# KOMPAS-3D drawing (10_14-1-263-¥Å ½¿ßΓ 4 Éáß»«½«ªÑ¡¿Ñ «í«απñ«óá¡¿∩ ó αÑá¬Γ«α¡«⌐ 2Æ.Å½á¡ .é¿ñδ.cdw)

Views: Вид 1, Вид 2, Вид 3
Referenced files in C:\Program Files\ASCON\KOMPAS-3D V10\Sys\: Graphic.lcs
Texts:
  Стена
  Металлич. перекрытия
  Сэндвич-панели 100
  Блоки фундаментные 400
  Сэндвич-панели 150
  Текст на чертеже
  Размерные надписи
  Шероховатость
  Линия-выноска #1
  Линия-выноска #2
  Линия-выноска #3
  Отклонения формы и база
  Заголовок таблицы
  Ячейка таблицы
  Стрелка вида
  Обозначение изменения
  Фигурная скобка
  Номер узла
  Марка координационной оси
  VRCB
  Выносная надпись
  Обозначение узла
  Марка/позиционное обозначение с линией-выноской
  Марка/позиционное обозначение на линии
  Марка/позиционное обозначение без линии-выноски
  Normal
  txt
  Body Text
  heading 1
  Знак Знак Знак Знак Знак Знак
  Verdana
  Лит-Масса-Масштаб
  Материал-Предприятие
  MS Sans Serif
  Simplex
  Txt
  Title Specification
  Body Specification ( left align )
  Body Specificaton ( centered )
  Без имени
  Additional DXF text style 0
  Обычный
  Термин
  Список определений
  Адрес
  Цитаты
  Форматированный
  Courier New
  Z-конец формы
  Z-начало формы
  ТекстШаг1
  Денис
  heading 2
  AGOpus
  footer
  Title
  ООббыыччнныыйй
  Definition Term
  Definition List
  Address
  Blockquote
  Preformatted
  z-Bottom of Form
  z-Top of Form
  TXT
  header
  heading 8
  heading 3
  heading 6
  heading 7
  russ
  ТТееррммиинн
  ССппииссоокк ооппррееддееллеенниийй
  ААддрреесс
  ЦЦииттааттыы
  ФФооррммааттиирроовваанннныыйй
  Z-ккооннеецц ффооррммыы
  Z-ннааччааллоо ффооррммыы
  Абзац Знак
  heading 4
  heading 5
  heading 9
  GOST 2.304 type A
  rustxt
  цепи
  ссылки
  Маркировка
  Подпись в квадратике
  табл
  ЗОНА_привяз
  маркировка
  ГОСТ_МНЕ
  ESK - Обозначение
  текст переноса
  Тексты. 3,2
  Body Text 3
  клеммы, контакты
  тексты табл
  ISOCP
  HeliosLight
  Pa3
  Pa1
  Шрифт 2.5
  Заголовки
  RUSTXT
  NormalParagraphStyle
  Три с половиной
  style2
  Table Contents
  Table Heading
  Tahoma
  FR5
  Текст 3,5
  Subtitle
  romanc
  eskd1
  Pa15
  Pa18
  CNBNDG+TimesNewRoman
  Аппараты
  подписи
  Состав чартежа
  ячейка табл.
  Ссылки
  Пояснения
  Клеммник текст
  CM12
  romans
  gif
  Пояснения 2
  текст табл
  ISOCPEUR
  CC С?т?и?л?ь? П?о? ц?е?н?т?р?у?
  Courier New Cyr
  ROMANS
  SIMPLEX
  Обычный (веб)
  .07 RGB_0_0_0 i0b0u0
  Body Text Indent 3
  Основной текст с отступом 3
  надписи
  экспликация
  Здание
  Оси
  Перечень оборудования
  Поз.
  Кол.
  ед., кг
  Приме-
  чание
  Реактор токоограничивающий 6 кВ
  РТСТ 6-3200-0,35 УХЛ3 (компл. 3 фазы)
  Опорный изолятор 10 кВ
  ИО-10-3,75-II-У3
  Проходной изолятор 10 кВ
  ИПУ-10/3150-12,5-УХЛ1
  Шина алюминиевая 2хAl-100 10
  Шкаф собственных нужд
  реакторной 2Т
  см. п.п.14
  см. п.п.4
  Примечания:
  1. Предусмотреть односкатную кровлю, со скатом в сторону оси А.
  2. Предусмотреть возможность демонтажа и повторной установки крыши и стены по оси 3 для
  ремонтных работ с реакторами.
  3. Предусмотреть несущую конструкцию  пола.
  4. В комплект поставки включить:
  - проходные изоляторы в количестве 6 шт.,
  - опорные изоляторы, жесткую ошиновку и арматуру для её крепления к изоляторам в количестве,
  достаточном для выполнения трассы разводки жесткой ошиновки по стенам и подключения
  реакторов,в соответствии с планом
  здания реакторной.
  - оборудование для организации силовой и осветительной сети в соответствии с 10/14-1-263-ЭП
  лист 6.
  - шкаф собственных нужд реакторной см. 10/14-1-263 лист 6.
  - крылечные металлическую лестницы.
  5. Выполнить разводку жесткой ошиновки по стенам, установку проходных изоляторов и крепление к
  ним ошиновки. Трасса разводки жесткой ошиновки должна удовлетворять требованиям ПУЭ 7 издание.
  Междуфазные расстояния принять не менее 500 мм ,длину пролета между опорными изоляторами
  принять не более 800 мм.
  6. Предусмотреть входные металлические двери- 2100х800 мм.
  7. Для предотвращения прикосновения к неизолированным токоведущим частям в здании реакторной
  предусмотреть съемное сетчатое ограждение высотой 1900 мм.
  8. На полу предусмотреть опалубку для заливки бетонной подушки.
  9. В полу под шкафом собственных нужд реакторной предусмотреть технологическое отверстия
  диаметром 60 мм.
  10. В местах подвеса  натяжных гирлянд предусмотреть усиление конструкции, с закладной деталью и
  узлом крепления типа КГП-7-1.
  11. Установку проходных изоляторов выполнить в соответствии с требованиями СНиП 3.05.06-85. Над
  проходными изоляторами по оси А предусмотреть защитный козырек.
  12. Предусмотреть естественную приточно-вытяжную и механическую вытяжную вентиляцию (см.
  10/14-1-263-ЭП, лист 6). Наклон жалюзей вентиляционных решеток см. узел 2.
  13. Освещение здания выполнить в соответствии с 10/14-1-263-ЭП, лист 6.
  14. Монтаж реакторов на бетонную подушку осуществляется подрядной организацией на месте
  установки реакторной.
  15. Пунктирной линией показано оборудование, не входящее в поставку завода.
  Сетчатое ограждение
  см п.п. 7
  Свайный фундамент
  см. 10/14-1-113-КС лист 11
  вентиляционная
  решетка 1500х1000
  Узел 1
  (увеличено)
  см. п.п.10
  Узел 2
  Жалюзи вентиляционной
  решетки
  POLYLINE_STYLE_0.73_RGB_0_0_0
  DIVIDE_RGB_0_0_0_SC_1_THICK_0.18
  DASHDOT1_RGB_0_0_0_SC_1_THICK_0.18
  осн 2
  K5LT_BASIC_RGB_0_0_255_THICK_0.3
  K5LT_AXLED_RGB_255_255_0_SC_1_THICK_0.09
  K5LT_REINFORCED_RGB_255_0_0_THICK_0.6
  POLYLINE_STYLE_0.30_RGB_0_0_255
  K5LT_THIN_RGB_0_0_0_THICK_0.09
  K5LT_THIN_INCLUDED_TO_HATCHING_RGB_0_0_0_THICK_0.09
  K5LT32769_RGB_0_0_0_THICK_0.09
  K5LT_THIN_RGB_0_0_0_THICK_0.13
  ACAD_ISO04W100_RGB_255_0_0_SC_1_THICK_0.13
  Стили документа
  Бетон
  Бетон 0
  Бетон 1
  Бетон 2
  Бетон 3
  Расположение оборудования в
  реакторной 2Т. План. Виды
  Н.контр.
  Разраб.
  Скахин
  Реконструкция ПС 110 кВ Опорная
  (замена трансформаторов 16МВА на 40МВА)
  Ведомость эскизного проекта
Dimensions and other numbers on the sheet: 10/14-1-263-ЭП; 5; 0; 7; 2,5; 3.5; 2.5; 1,8; 2,5 (контакты, клеммы); 2.5 курсив; 2,5_3; 3,2 (надписи); 3,5_01; 2,5_01; 3,5_tabl; 5_заголовок; 2,3_; 3,2_; 3,2_зона не привяз; 2,5 грязносинь; 5,0_белый_подчёркнутый; 3,2; 3.2 фиол; 3,5; 3,2 элементы; 3,2 линия; 3,2 таблица; 3.2 маркировка; 2.5_Э5_надписи; 2.5_Э5_ссылки; 2.5_кабель; 3.2; 2.5 надписи; 3,2 (Зоны); 3 и 5; 3.2 (текст); 0 i0b0u0; 1; 2; 3; 4; 10/14-1-263-ЭП лист 6; 6; 1630; 750; 4500; 500; 1430; 1015; 1750; 4200; 300; 800; 2090; 600; 1100; 6900; 6250; 1270; 1135; 1445; 430; 1380; 1460; 1450; 100; 1035; 835; 650; 1610; 1680; 77; 11.12; 10/14-1-ИОС7.1-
